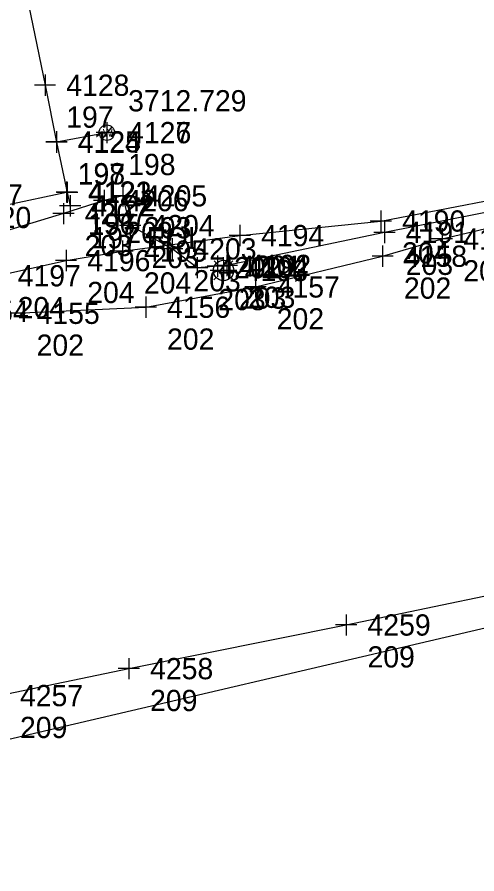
# Model space of a CAD drawing. Extents: x 352921 to 392463, y 10654752 to 10749237.
# Drawn here: x 385379.5 to 385487.7, y 10655037.4 to 10655239 of the extents above; entities that cross this region are included whole.
import ezdxf

# ---------------------------------------------------------------- set-up
doc = ezdxf.new("R2010")
doc.units = 0
for name, color, linetype in [('GAS', 7, 'Continuous'), ('GAS_#', 7, 'Continuous'), ('GAS_DES', 7, 'Continuous'), ('GAS_SPOT', 7, 'Continuous'), ('LIMITS', 7, 'Continuous'), ('TELE', 7, 'Continuous'), ('TELE_#', 7, 'Continuous'), ('TELE_DES', 7, 'Continuous'), ('TELE_SPOT', 7, 'Continuous'), ('UE', 7, 'Continuous'), ('UE_#', 7, 'Continuous'), ('UE_DES', 7, 'Continuous'), ('UE_SPOT', 7, 'Continuous'), ('W_#', 7, 'Continuous'), ('W_DES', 7, 'Continuous'), ('W_ELEV', 7, 'Continuous'), ('W_SPOT', 7, 'Continuous'), ('WATER', 7, 'Continuous')]:
    doc.layers.add(name, color=color, linetype=linetype)

msp = doc.modelspace()

# ---------------------------------------------------------------- linework, layer by layer
at = {"layer": 'GAS'}
msp.add_lwpolyline([(385173.81, 10655043.87), (385216.2, 10655050.74), (385257.04, 10655056.97), (385285.37, 10655062.36), (385319.37, 10655068.62), (385350.72, 10655074.96), (385375.14, 10655079.33), (385405.78, 10655085.67), (385456.98, 10655095.94), (385511.99, 10655107.46), (385548.92, 10655114.47), (385556.39, 10655116.22), (385576.96, 10655119.71), (385602.62, 10655123.75), (385627.18, 10655128.52), (385661.55, 10655135.28)], dxfattribs=at)
at = {"layer": 'GAS_SPOT'}
for p, q in [((385456.98, 10655098.44), (385456.98, 10655093.44)), ((385459.48, 10655095.94), (385454.48, 10655095.94)), ((385405.78, 10655088.17), (385405.78, 10655083.17)), ((385408.28, 10655085.67), (385403.28, 10655085.67))]:
    msp.add_line(p, q, dxfattribs=at)
at = {"layer": 'LIMITS'}
msp.add_line((385241.9, 10655037.37), (385660.63, 10655135.2), dxfattribs=at)
at = {"layer": 'TELE'}
for points in [[(385343.16, 10655171.64), (385346.01, 10655171.93), (385359.6, 10655174.83), (385374.59, 10655178.13), (385390.98, 10655181.7), (385404.32, 10655183.94), (385431.93, 10655187.59), (385465.13, 10655191.02), (385507.45, 10655199.13), (385537.19, 10655205.55), (385584.2, 10655215.42), (385630.6, 10655226.99), (385644.43, 10655232.42)], [(385343.41, 10655170.63), (385348.89, 10655169.66), (385362.32, 10655169.75), (385379.05, 10655169.3), (385409.77, 10655170.73), (385435.6, 10655175.5), (385465.55, 10655182.73), (385479.53, 10655186.8), (385509.79, 10655193.93), (385538.35, 10655200.45), (385563.55, 10655203.67), (385593.08, 10655208.62), (385612.99, 10655212.29), (385633.75, 10655217.67), (385646.35, 10655222.59)]]:
    msp.add_lwpolyline(points, dxfattribs=at)
at = {"layer": 'TELE_SPOT'}
for p, q in [((385465.13, 10655193.52), (385465.13, 10655188.52)), ((385431.93, 10655190.09), (385431.93, 10655185.09)), ((385467.63, 10655191.02), (385462.63, 10655191.02)), ((385479.53, 10655189.3), (385479.53, 10655184.3)), ((385404.32, 10655186.44), (385404.32, 10655181.44)), ((385434.43, 10655187.59), (385429.43, 10655187.59)), ((385482.03, 10655186.8), (385477.03, 10655186.8)), ((385390.98, 10655184.2), (385390.98, 10655179.2)), ((385406.82, 10655183.94), (385401.82, 10655183.94)), ((385465.55, 10655185.23), (385465.55, 10655180.23)), ((385468.05, 10655182.73), (385463.05, 10655182.73)), ((385393.48, 10655181.7), (385388.48, 10655181.7)), ((385435.6, 10655178), (385435.6, 10655173)), ((385438.1, 10655175.5), (385433.1, 10655175.5)), ((385409.77, 10655173.23), (385409.77, 10655168.23)), ((385412.27, 10655170.73), (385407.27, 10655170.73)), ((385381.55, 10655169.3), (385376.55, 10655169.3))]:
    msp.add_line(p, q, dxfattribs=at)
at = {"layer": 'UE'}
for p, q in [((385428.08, 10655181.77), (385428.08, 10655182.53)), ((385426.4, 10655181.09), (385425.86, 10655181.63)), ((385429.75, 10655181.09), (385430.29, 10655181.63)), ((385424.91, 10655179.42), (385425.67, 10655179.42)), ((385430.48, 10655179.42), (385431.24, 10655179.42)), ((385425.81, 10655177.15), (385426.35, 10655177.69)), ((385428.08, 10655176.2), (385428.08, 10655176.96)), ((385430.34, 10655177.15), (385429.8, 10655177.69))]:
    msp.add_line(p, q, dxfattribs=at)
msp.add_lwpolyline([(385643.23, 10655225.63), (385622.67, 10655220.72), (385585.21, 10655213.37), (385538.06, 10655203.36), (385503.63, 10655195.79), (385465.99, 10655188.33), (385428.84, 10655180.57), (385426.69, 10655180.39), (385421.84, 10655180.03), (385415.98, 10655184.46), (385406.1, 10655189.93), (385404.34, 10655196.94), (385399.96, 10655195.82), (385390.37, 10655192.75), (385349.6, 10655180.37), (385345.3, 10655178.24), (385334.4, 10655171.89), (385329.22, 10655169.21), (385312.26, 10655162.34), (385301.39, 10655157.79)], dxfattribs=at)
msp.add_circle((385428.08, 10655179.37), 2.4, dxfattribs=at)
msp.add_circle((385428.08, 10655179.37), 2.4, dxfattribs=at)
at = {"layer": 'UE_SPOT'}
for p, q in [((385399.96, 10655198.32), (385399.96, 10655193.32)), ((385404.34, 10655199.44), (385404.34, 10655194.44)), ((385406.84, 10655196.94), (385401.84, 10655196.94)), ((385390.37, 10655195.25), (385390.37, 10655190.25)), ((385402.46, 10655195.82), (385397.46, 10655195.82)), ((385392.87, 10655192.75), (385387.87, 10655192.75)), ((385406.1, 10655192.43), (385406.1, 10655187.43)), ((385408.6, 10655189.93), (385403.6, 10655189.93)), ((385465.99, 10655190.83), (385465.99, 10655185.83)), ((385468.49, 10655188.33), (385463.49, 10655188.33)), ((385415.98, 10655186.96), (385415.98, 10655181.96)), ((385418.48, 10655184.46), (385413.48, 10655184.46)), ((385421.84, 10655182.53), (385421.84, 10655177.53)), ((385426.69, 10655182.89), (385426.69, 10655177.89)), ((385428.08, 10655181.87), (385428.08, 10655176.87)), ((385428.84, 10655183.07), (385428.84, 10655178.07)), ((385424.34, 10655180.03), (385419.34, 10655180.03)), ((385429.19, 10655180.39), (385424.19, 10655180.39)), ((385431.34, 10655180.57), (385426.34, 10655180.57)), ((385430.58, 10655179.37), (385425.58, 10655179.37))]:
    msp.add_line(p, q, dxfattribs=at)
at = {"layer": 'W_SPOT'}
for p, q in [((385386.03, 10655225.48), (385386.03, 10655220.48)), ((385388.53, 10655222.98), (385383.53, 10655222.98)), ((385400.6, 10655214.32), (385400.6, 10655209.32)), ((385400.61, 10655214.32), (385400.61, 10655209.32)), ((385388.74, 10655212.15), (385388.74, 10655207.15)), ((385388.73, 10655212.04), (385388.73, 10655207.04)), ((385403.1, 10655211.82), (385398.1, 10655211.82)), ((385403.11, 10655211.82), (385398.11, 10655211.82)), ((385391.23, 10655209.54), (385386.23, 10655209.54)), ((385391.24, 10655209.65), (385386.24, 10655209.65)), ((385391.13, 10655200.34), (385391.13, 10655195.34)), ((385391.26, 10655200.26), (385391.26, 10655195.26)), ((385393.63, 10655197.84), (385388.63, 10655197.84)), ((385393.76, 10655197.76), (385388.76, 10655197.76)), ((385391.98, 10655197.09), (385391.98, 10655192.09)), ((385394.48, 10655194.59), (385389.48, 10655194.59))]:
    msp.add_line(p, q, dxfattribs=at)
at = {"layer": 'WATER'}
for p, q in [((385401.74, 10655213.22), (385399.53, 10655210.34)), ((385388.74, 10655209.65), (385400.61, 10655211.82))]:
    msp.add_line(p, q, dxfattribs=at)
for points in [[(385345.59, 10655412.99), (385350.49, 10655387.33), (385354.02, 10655368.5), (385356.7, 10655356.34), (385361.4, 10655335.29), (385367.85, 10655302.68), (385371.7, 10655285.65), (385380.23, 10655251.18), (385386.03, 10655222.98), (385388.73, 10655209.54), (385391.26, 10655197.76), (385391.98, 10655194.59)], [(385347.9, 10655189.64), (385362.92, 10655191.86), (385391.13, 10655197.84)]]:
    msp.add_lwpolyline(points, dxfattribs=at)
msp.add_circle((385400.6, 10655211.82), 1.82, dxfattribs=at)
msp.add_circle((385400.6, 10655211.82), 1.82, dxfattribs=at)

# ---------------------------------------------------------------- texts
at = {"layer": 'GAS_#'}
for s, p in [('4259', (385461.98, 10655093.44)), ('4258', (385410.78, 10655083.17)), ('4257', (385380.14, 10655076.83))]:
    msp.add_text(s, height=5, dxfattribs=at).set_placement(p)
at = {"layer": 'GAS_DES'}
for p in [(385461.98, 10655085.94), (385410.78, 10655075.67), (385380.14, 10655069.33)]:
    msp.add_text('209', height=5, dxfattribs=at).set_placement(p)
at = {"layer": 'TELE_#'}
for s, p in [('4190', (385470.13, 10655188.52)), ('4194', (385436.93, 10655185.09)), ('4159', (385484.53, 10655184.3)), ('4195', (385409.32, 10655181.44)), ('4196', (385395.98, 10655179.2)), ('4158', (385470.55, 10655180.23)), ('4197', (385379.59, 10655175.63)), ('4157', (385440.6, 10655173)), ('4154', (385367.32, 10655167.25)), ('4155', (385384.05, 10655166.8)), ('4156', (385414.77, 10655168.23))]:
    msp.add_text(s, height=5, dxfattribs=at).set_placement(p)
at = {"layer": 'TELE_DES'}
for s, p in [('204', (385470.13, 10655181.02)), ('204', (385436.93, 10655177.59)), ('202', (385484.53, 10655176.8)), ('204', (385409.32, 10655173.94)), ('204', (385395.98, 10655171.7)), ('202', (385470.55, 10655172.73)), ('204', (385379.59, 10655168.13)), ('202', (385440.6, 10655165.5)), ('202', (385414.77, 10655160.73)), ('202', (385384.05, 10655159.3))]:
    msp.add_text(s, height=5, dxfattribs=at).set_placement(p)
at = {"layer": 'UE_#'}
for s, p in [('4206', (385404.96, 10655193.32)), ('4205', (385409.34, 10655194.44)), ('4207', (385395.37, 10655190.25)), ('4204', (385411.1, 10655187.43)), ('4191', (385470.99, 10655185.83)), ('4203', (385420.98, 10655181.96)), ('4202', (385426.84, 10655177.53)), ('4201', (385431.69, 10655177.89)), ('4193', (385433.08, 10655176.87)), ('4192', (385433.84, 10655178.07))]:
    msp.add_text(s, height=5, dxfattribs=at).set_placement(p)
at = {"layer": 'UE_DES'}
for p in [(385409.34, 10655186.94), (385404.96, 10655185.82), (385395.37, 10655182.75), (385411.1, 10655179.93), (385470.99, 10655178.33), (385420.98, 10655174.46), (385426.84, 10655170.03), (385431.69, 10655170.39), (385433.84, 10655170.57)]:
    msp.add_text('203', height=5, dxfattribs=at).set_placement(p)
at = {"layer": 'W_#'}
for s, p in [('4128', (385391.03, 10655220.48)), ('4126', (385405.61, 10655209.32)), ('4127', (385405.6, 10655209.32)), ('4124', (385393.73, 10655207.04)), ('4125', (385393.74, 10655207.15)), ('4121', (385396.13, 10655195.34)), ('4123', (385396.26, 10655195.26)), ('4122', (385396.98, 10655192.09)), ('4120', (385367.92, 10655189.36))]:
    msp.add_text(s, height=5, dxfattribs=at).set_placement(p)
at = {"layer": 'W_DES'}
for s, p in [('197', (385391.03, 10655212.98)), ('198', (385405.61, 10655201.82)), ('197', (385393.73, 10655199.54)), ('198', (385393.74, 10655199.65)), ('196', (385396.13, 10655187.84)), ('197', (385396.26, 10655187.76)), ('197 EOI', (385396.98, 10655184.59))]:
    msp.add_text(s, height=5, dxfattribs=at).set_placement(p)
at = {"layer": 'W_ELEV'}
for s, p in [('3712.729', (385405.6, 10655216.82)), ('3712.957', (385352.92, 10655194.67))]:
    msp.add_text(s, height=5, dxfattribs=at).set_placement(p)
at = {"layer": 'WATER'}
msp.add_text('W', height=1.82, dxfattribs=at).set_placement((385399.66, 10655210.87))

doc.saveas('drawing.dxf')
